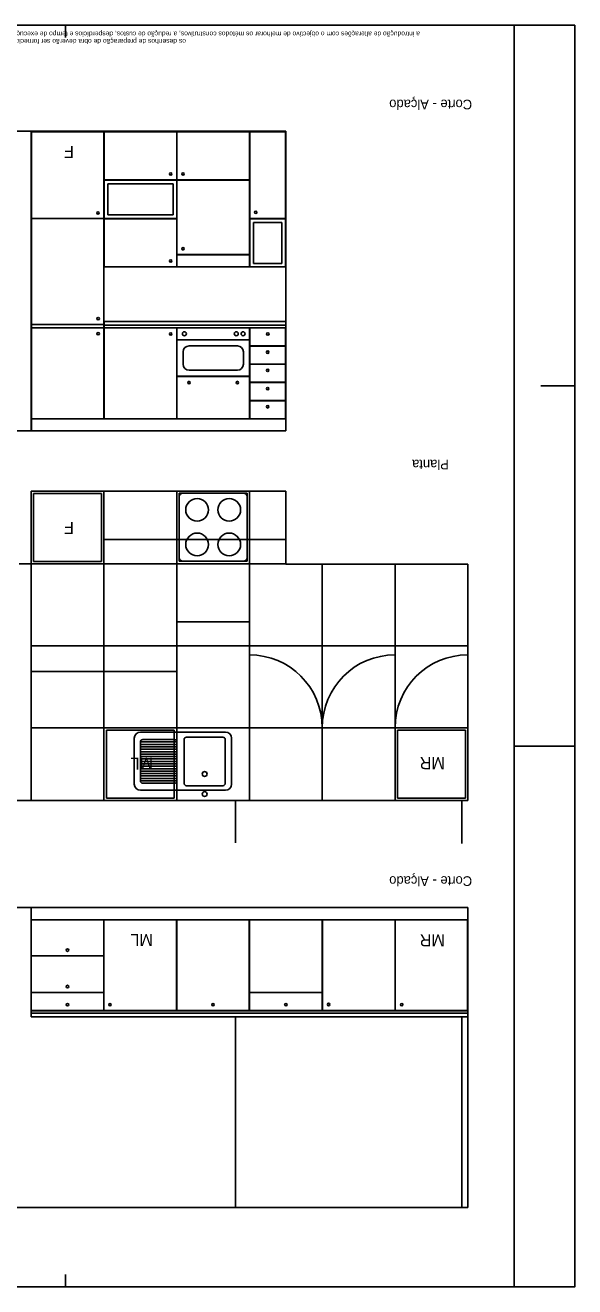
# Model space of a CAD drawing. Extents: x 1329.4 to 1341, y -313.7 to -303.3.
# Drawn here: x 1336.46 to 1340.99, y -313.71 to -303.32 of the extents above; entities that cross this region are included whole.
import ezdxf

# ---------------------------------------------------------------- set-up
doc = ezdxf.new("R2010")
doc.units = 0
for name, color, linetype in [('Level 1', 7, 'Continuous'), ('Level 10', 7, 'Continuous'), ('Level 11', 7, 'Continuous'), ('Level 13', 7, 'Continuous'), ('Level 2', 7, 'Continuous'), ('Level 3', 7, 'Continuous'), ('Level 4', 7, 'Continuous'), ('Level 60', 7, 'Continuous'), ('Level 62', 7, 'Continuous')]:
    doc.layers.add(name, color=color, linetype=linetype)

msp = doc.modelspace()

# ---------------------------------------------------------------- linework, layer by layer
at = {"layer": 'Level 1'}
for p, q in [((1338.607, -304.19), (1332.257, -304.19)), ((1338.607, -304.19), (1338.607, -306.66)), ((1338.607, -306.66), (1332.257, -306.66)), ((1338.607, -307.156), (1336.507, -307.156)), ((1336.507, -307.156), (1336.507, -307.756)), ((1338.607, -307.156), (1336.507, -307.156)), ((1336.507, -307.156), (1336.507, -307.756)), ((1338.607, -307.156), (1336.507, -307.156)), ((1336.507, -307.156), (1336.507, -307.756)), ((1338.607, -307.156), (1338.607, -307.759)), ((1338.607, -307.156), (1338.607, -307.759)), ((1338.607, -307.156), (1338.607, -307.759)), ((1336.507, -307.756), (1336.407, -307.756)), ((1338.607, -307.759), (1340.107, -307.759)), ((1340.107, -307.759), (1340.107, -309.706)), ((1336.247, -309.706), (1338.191, -309.706)), ((1338.191, -309.706), (1338.191, -310.056)), ((1340.107, -309.706), (1340.057, -309.706)), ((1340.057, -309.706), (1340.057, -310.059)), ((1340.107, -310.589), (1332.257, -310.589)), ((1340.107, -310.589), (1340.107, -313.059)), ((1340.107, -313.059), (1332.257, -313.059))]:
    msp.add_line(p, q, dxfattribs=at)
at = {"layer": 'Level 10'}
for p, q in [((1336.507, -309.106), (1336.507, -307.756)), ((1337.107, -309.106), (1337.107, -307.756)), ((1337.707, -309.106), (1337.707, -307.756)), ((1338.307, -309.106), (1338.307, -307.756)), ((1338.907, -309.106), (1338.907, -307.759)), ((1339.507, -309.106), (1339.507, -307.759)), ((1340.107, -308.432), (1336.507, -308.432))]:
    msp.add_line(p, q, dxfattribs=at)
at = {"layer": 'Level 11'}
for p, q in [((1337.087, -307.176), (1336.527, -307.176)), ((1336.527, -307.736), (1336.527, -307.176)), ((1337.087, -307.736), (1337.087, -307.176)), ((1337.727, -307.704), (1337.727, -307.204)), ((1338.257, -307.174), (1337.757, -307.174)), ((1338.287, -307.704), (1338.287, -307.204)), ((1336.527, -307.736), (1337.087, -307.736)), ((1338.257, -307.734), (1337.757, -307.734)), ((1337.407, -309.544), (1337.407, -309.224)), ((1337.709, -309.224), (1337.407, -309.224)), ((1337.709, -309.244), (1337.407, -309.244)), ((1337.689, -309.204), (1337.427, -309.204)), ((1337.709, -309.544), (1337.709, -309.224)), ((1337.767, -309.204), (1337.767, -309.564)), ((1338.087, -309.184), (1337.787, -309.184)), ((1338.107, -309.564), (1338.107, -309.204)), ((1337.709, -309.264), (1337.407, -309.264)), ((1337.709, -309.284), (1337.407, -309.284)), ((1337.709, -309.304), (1337.407, -309.304)), ((1337.709, -309.324), (1337.407, -309.324)), ((1337.709, -309.344), (1337.407, -309.344)), ((1337.709, -309.364), (1337.407, -309.364)), ((1337.709, -309.384), (1337.407, -309.384)), ((1337.709, -309.404), (1337.407, -309.404)), ((1337.709, -309.424), (1337.407, -309.424)), ((1337.709, -309.444), (1337.407, -309.444)), ((1337.709, -309.464), (1337.407, -309.464)), ((1337.709, -309.484), (1337.407, -309.484)), ((1337.709, -309.504), (1337.407, -309.504)), ((1337.709, -309.524), (1337.407, -309.524)), ((1337.709, -309.544), (1337.407, -309.544)), ((1337.689, -309.564), (1337.427, -309.564)), ((1337.787, -309.584), (1338.087, -309.584))]:
    msp.add_line(p, q, dxfattribs=at)
for points in [[(1337.407, -309.143), (1338.109, -309.143)], [(1337.357, -309.571), (1337.357, -309.193)], [(1338.159, -309.193), (1338.159, -309.571)], [(1338.109, -309.621), (1337.407, -309.621)]]:
    msp.add_lwpolyline(points, dxfattribs=at)
for centre, radius in [((1337.875, -307.311), 0.0936), ((1338.14, -307.311), 0.0936), ((1337.875, -307.596), 0.0936), ((1338.14, -307.596), 0.0936), ((1337.937, -309.488), 0.0199), ((1337.937, -309.653), 0.0199)]:
    msp.add_circle(centre, radius, dxfattribs=at)
for centre, radius, start, end in [((1337.757, -307.204), 0.03, 90.0002, 180), ((1338.257, -307.204), 0.03, 359.9999, 90.0002), ((1337.757, -307.704), 0.03, 180.0001, 270), ((1338.257, -307.704), 0.03, 270.0001, 0.0001), ((1337.407, -309.193), 0.05, 90, 180), ((1338.109, -309.193), 0.05, 0, 90), ((1337.427, -309.224), 0.02, 90, 180), ((1337.689, -309.224), 0.02, 0, 90), ((1337.787, -309.204), 0.02, 90, 180), ((1338.087, -309.204), 0.02, 0, 90), ((1337.427, -309.544), 0.02, 180, 270), ((1337.689, -309.544), 0.02, 270, 0), ((1337.407, -309.571), 0.05, 180, 270), ((1337.787, -309.564), 0.02, 180, 270), ((1338.087, -309.564), 0.02, 270, 0), ((1338.109, -309.571), 0.05, 270, 0)]:
    msp.add_arc(centre, radius, start, end, dxfattribs=at)
at = {"layer": 'Level 13'}
for p, q in [((1338.607, -304.195), (1336.507, -304.195)), ((1336.509, -304.911), (1336.509, -304.195)), ((1337.107, -304.91), (1337.107, -304.195)), ((1337.109, -304.593), (1337.109, -304.195)), ((1337.707, -304.593), (1337.707, -304.195)), ((1337.709, -304.593), (1337.709, -304.195)), ((1338.307, -304.593), (1338.307, -304.195)), ((1338.309, -304.91), (1338.309, -304.195)), ((1338.605, -304.195), (1338.605, -305.31)), ((1337.707, -304.593), (1337.109, -304.593)), ((1337.109, -304.91), (1337.109, -304.595)), ((1337.707, -304.595), (1337.109, -304.595)), ((1337.677, -304.625), (1337.139, -304.625)), ((1337.139, -304.88), (1337.139, -304.625)), ((1337.677, -304.88), (1337.677, -304.625)), ((1337.707, -304.91), (1337.707, -304.595)), ((1338.307, -304.593), (1337.709, -304.593)), ((1338.307, -304.595), (1337.709, -304.595)), ((1337.709, -305.208), (1337.709, -304.595)), ((1338.307, -305.208), (1338.307, -304.595)), ((1337.677, -304.88), (1337.139, -304.88)), ((1337.107, -304.91), (1336.509, -304.91)), ((1337.107, -304.911), (1336.509, -304.911)), ((1336.509, -306.66), (1336.509, -304.911)), ((1337.107, -306.56), (1337.107, -304.911)), ((1337.107, -306.56), (1337.107, -304.925)), ((1337.707, -304.91), (1337.109, -304.91)), ((1337.109, -305.31), (1337.109, -304.912)), ((1337.707, -304.912), (1337.109, -304.912)), ((1337.707, -305.31), (1337.707, -304.912)), ((1338.605, -304.91), (1338.309, -304.91)), ((1338.309, -305.31), (1338.309, -304.912)), ((1338.605, -304.912), (1338.309, -304.912)), ((1338.575, -304.942), (1338.339, -304.942)), ((1338.339, -305.28), (1338.339, -304.942)), ((1338.575, -304.942), (1338.575, -305.28)), ((1338.307, -305.208), (1337.709, -305.208)), ((1338.307, -305.21), (1337.709, -305.21)), ((1337.709, -305.31), (1337.709, -305.21)), ((1338.307, -305.31), (1338.307, -305.21)), ((1338.575, -305.28), (1338.339, -305.28)), ((1338.607, -305.31), (1337.109, -305.31)), ((1337.107, -305.785), (1336.509, -305.785)), ((1337.107, -305.81), (1336.509, -305.81)), ((1338.607, -305.76), (1337.109, -305.76)), ((1337.109, -306.56), (1337.109, -305.76)), ((1338.607, -305.79), (1337.109, -305.79)), ((1338.607, -305.81), (1337.109, -305.81)), ((1337.707, -305.812), (1337.109, -305.812)), ((1337.707, -306.56), (1337.707, -305.812)), ((1337.709, -306.21), (1337.709, -305.81)), ((1338.307, -306.21), (1338.307, -305.81)), ((1338.605, -305.812), (1338.309, -305.812)), ((1338.309, -305.96), (1338.309, -305.812)), ((1338.605, -305.812), (1338.605, -305.96)), ((1338.307, -305.91), (1337.709, -305.91)), ((1337.759, -306.11), (1337.759, -306.01)), ((1338.207, -305.96), (1337.809, -305.96)), ((1338.257, -306.11), (1338.257, -306.01)), ((1338.605, -305.96), (1338.309, -305.96)), ((1338.309, -306.11), (1338.309, -305.962)), ((1338.605, -305.962), (1338.309, -305.962)), ((1338.605, -305.962), (1338.605, -306.11)), ((1338.605, -306.11), (1338.309, -306.11)), ((1338.309, -306.26), (1338.309, -306.112)), ((1338.605, -306.112), (1338.309, -306.112)), ((1338.605, -306.112), (1338.605, -306.26)), ((1338.307, -306.21), (1337.709, -306.21)), ((1338.307, -306.212), (1337.709, -306.212)), ((1337.709, -306.56), (1337.709, -306.212)), ((1338.207, -306.16), (1337.809, -306.16)), ((1338.307, -306.56), (1338.307, -306.212)), ((1338.605, -306.26), (1338.309, -306.26)), ((1338.309, -306.41), (1338.309, -306.262)), ((1338.605, -306.262), (1338.309, -306.262)), ((1338.605, -306.262), (1338.605, -306.41)), ((1338.605, -306.41), (1338.309, -306.41)), ((1338.309, -306.56), (1338.309, -306.412)), ((1338.605, -306.412), (1338.309, -306.412)), ((1338.605, -306.412), (1338.605, -306.56)), ((1337.107, -306.56), (1336.509, -306.56)), ((1338.607, -306.56), (1337.107, -306.56)), ((1336.507, -310.589), (1336.507, -311.489)), ((1340.107, -310.689), (1336.507, -310.689)), ((1337.105, -310.689), (1337.105, -310.985)), ((1337.107, -310.689), (1337.107, -311.437)), ((1337.705, -310.689), (1337.705, -311.437)), ((1337.707, -310.689), (1337.707, -311.437)), ((1338.305, -310.689), (1338.305, -311.437)), ((1338.307, -310.689), (1338.307, -311.287)), ((1338.907, -310.689), (1338.907, -311.287)), ((1338.909, -310.689), (1338.909, -311.437)), ((1339.507, -310.689), (1339.507, -311.437)), ((1339.509, -310.689), (1339.509, -311.437)), ((1340.105, -310.689), (1340.105, -311.437)), ((1337.105, -310.985), (1336.507, -310.985)), ((1337.105, -310.987), (1336.507, -310.987)), ((1337.105, -310.987), (1337.105, -311.287)), ((1337.105, -311.287), (1336.507, -311.287)), ((1337.105, -311.289), (1336.507, -311.289)), ((1337.105, -311.289), (1337.105, -311.437)), ((1338.907, -311.287), (1338.307, -311.287)), ((1338.907, -311.289), (1338.307, -311.289)), ((1338.307, -311.289), (1338.307, -311.437)), ((1338.907, -311.289), (1338.907, -311.437)), ((1337.105, -311.437), (1336.507, -311.437)), ((1340.107, -311.439), (1336.507, -311.439)), ((1340.107, -311.459), (1336.507, -311.459)), ((1340.107, -311.489), (1336.507, -311.489)), ((1337.705, -311.437), (1337.107, -311.437)), ((1338.305, -311.437), (1337.707, -311.437)), ((1338.907, -311.437), (1338.307, -311.437)), ((1340.105, -311.437), (1338.909, -311.437))]:
    msp.add_line(p, q, dxfattribs=at)
for centre, radius in [((1337.657, -304.543), 0.01), ((1337.759, -304.543), 0.01), ((1337.057, -304.865), 0.01), ((1338.359, -304.859), 0.01), ((1337.759, -305.16), 0.01), ((1337.657, -305.26), 0.01), ((1337.059, -305.735), 0.01), ((1337.059, -305.86), 0.01), ((1337.657, -305.862), 0.01), ((1337.77, -305.86), 0.0162), ((1338.198, -305.86), 0.0162), ((1338.254, -305.86), 0.0162), ((1338.458, -305.862), 0.01), ((1338.457, -306.012), 0.01), ((1338.457, -306.162), 0.01), ((1337.809, -306.262), 0.01), ((1338.207, -306.262), 0.01), ((1338.457, -306.312), 0.01), ((1338.457, -306.462), 0.01), ((1336.806, -310.939), 0.01), ((1336.806, -311.239), 0.01), ((1336.806, -311.389), 0.01), ((1337.156, -311.389), 0.01), ((1338.006, -311.389), 0.01), ((1338.607, -311.389), 0.01), ((1338.959, -311.387), 0.01), ((1339.563, -311.389), 0.01)]:
    msp.add_circle(centre, radius, dxfattribs=at)
for centre, start, end in [((1337.809, -306.01), 90, 180), ((1338.207, -306.01), 0, 90), ((1337.809, -306.11), 180, 270), ((1338.207, -306.11), 270, 0)]:
    msp.add_arc(centre, 0.05, start, end, dxfattribs=at)
at = {"layer": 'Level 2'}
for p, q in [((1336.507, -306.66), (1336.507, -304.19)), ((1336.507, -307.756), (1336.507, -307.156)), ((1336.507, -307.756), (1336.507, -307.156)), ((1336.507, -307.756), (1336.507, -307.156)), ((1337.107, -307.756), (1337.107, -307.156)), ((1338.607, -307.756), (1336.507, -307.756)), ((1340.107, -309.106), (1336.507, -309.106)), ((1336.507, -309.106), (1336.507, -309.706)), ((1338.191, -309.706), (1340.057, -309.706)), ((1338.191, -311.489), (1338.191, -313.059)), ((1340.057, -311.489), (1340.057, -313.059))]:
    msp.add_line(p, q, dxfattribs=at)
at = {"layer": 'Level 3'}
for p, q in [((1338.607, -307.556), (1337.107, -307.556)), ((1338.307, -308.233), (1337.707, -308.233)), ((1337.107, -308.644), (1336.507, -308.644)), ((1337.707, -308.644), (1337.107, -308.644))]:
    msp.add_line(p, q, dxfattribs=at)
for centre, radius, start, end in [((1338.307, -309.106), 0.6, 0, 90), ((1339.507, -309.106), 0.6, 90, 180), ((1340.107, -309.106), 0.6, 90, 180), ((1337.268, -309.106), 0.443, 0, 2.777777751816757e-06), ((1339.667, -309.106), 0.443, 0, 2.777777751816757e-06)]:
    msp.add_arc(centre, radius, start, end, dxfattribs=at)
at = {"layer": 'Level 4'}
for p, q in [((1337.707, -307.154), (1337.707, -307.754)), ((1338.307, -307.154), (1338.307, -307.754)), ((1337.727, -307.174), (1337.727, -307.734)), ((1338.287, -307.174), (1337.727, -307.174)), ((1338.287, -307.174), (1338.287, -307.734)), ((1337.727, -307.734), (1338.287, -307.734)), ((1337.107, -309.106), (1337.107, -309.706)), ((1337.107, -309.106), (1337.107, -309.706)), ((1337.127, -309.126), (1337.127, -309.686)), ((1337.127, -309.126), (1337.687, -309.126)), ((1337.687, -309.126), (1337.687, -309.686)), ((1337.707, -309.106), (1337.707, -309.706)), ((1337.707, -309.106), (1337.707, -309.706)), ((1338.307, -309.106), (1338.307, -309.706)), ((1338.907, -309.106), (1338.907, -309.706)), ((1339.507, -309.106), (1339.507, -309.706)), ((1339.507, -309.106), (1339.507, -309.706)), ((1339.527, -309.126), (1339.527, -309.686)), ((1339.527, -309.126), (1340.087, -309.126)), ((1340.087, -309.126), (1340.087, -309.686)), ((1340.107, -309.106), (1340.107, -309.706)), ((1340.107, -309.106), (1340.107, -309.706)), ((1337.127, -309.686), (1337.687, -309.686)), ((1339.527, -309.686), (1340.087, -309.686))]:
    msp.add_line(p, q, dxfattribs=at)
at = {"layer": 'Level 62'}
for p, q in [((1336.79, -303.418), (1336.79, -303.318)), ((1340.49, -313.713), (1340.49, -303.318)), ((1340.99, -306.288), (1340.71, -306.288)), ((1340.49, -309.258), (1340.99, -309.258)), ((1336.789, -313.613), (1336.789, -313.713)), ((1340.49, -313.713), (1340.99, -313.713))]:
    msp.add_line(p, q, dxfattribs=at)
msp.add_lwpolyline([(1340.99, -303.318), (1340.99, -313.713), (1329.39, -313.713), (1329.39, -303.318)], close=True, dxfattribs=at)

# ---------------------------------------------------------------- texts
at = {"layer": 'Level 11'}
for s, p in [('F', (1336.859, -304.312)), ('F', (1336.859, -307.41)), ('ML', (1337.512, -309.353)), ('MR', (1339.918, -309.348)), ('ML', (1337.511, -310.806)), ('MR', (1339.918, -310.808))]:
    msp.add_text(s, height=0.1, rotation=180, dxfattribs=at).set_placement(p)
at = {"layer": 'Level 60'}
for s, p in [('Corte - Alçado', (1340.143, -303.931)), ('Planta', (1339.951, -306.898)), ('Corte - Alçado', (1340.143, -310.33))]:
    msp.add_text(s, height=0.08, rotation=180, dxfattribs=at).set_placement(p)
at = {"layer": 'Level 62'}
for s, p in [('os desenhos de preparação de obra deverão ser fornecidos ao projectista para sua aprovação -', (1337.783, -303.431)), ('a introdução de alterações com o objectivo de melhorar os métodos construtivos, a redução de custos, desperdícios e tempo de execução, observadas pelos exe', (1339.712, -303.37))]:
    msp.add_text(s, height=0.04, rotation=180, dxfattribs=at).set_placement(p)

doc.saveas('drawing.dxf')
